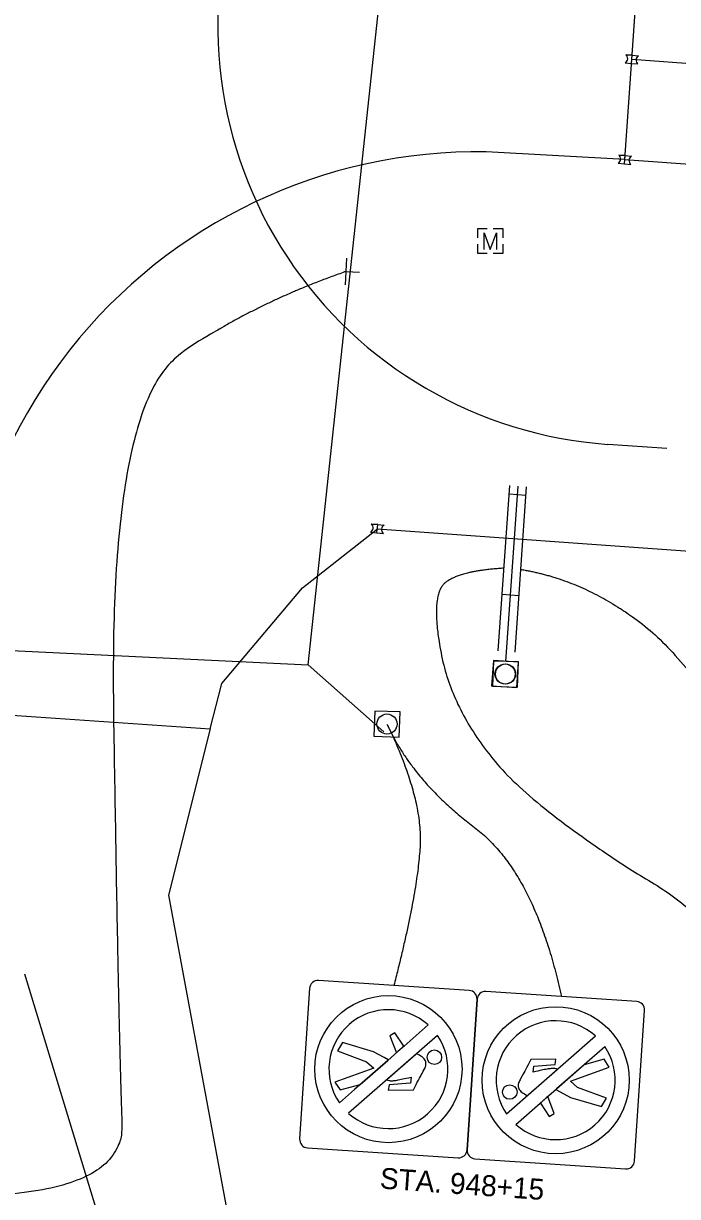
# Model space of a CAD drawing. Extents: x 1847379 to 1850904, y 217032 to 220169.
# Drawn here: x 1848911.4 to 1848989.3, y 218737.1 to 218877.1 of the extents above; entities that cross this region are included whole.
import ezdxf

# ---------------------------------------------------------------- set-up
doc = ezdxf.new("R2010")
doc.units = 0
for name, color, linetype in [('BR_P_Gen_Approach_Slab_Hidden', 7, 'Continuous'), ('BR_P_Gen_Phase_Construction', 7, 'Continuous'), ('PM_P_Cells', 7, 'Continuous'), ('PM_P_Channelizing_Line', 7, 'Continuous'), ('PM_P_Dotted_Line', 7, 'Continuous'), ('PM_P_Edge_Line', 7, 'Continuous'), ('PM_P_Lane_Line', 7, 'Continuous'), ('PM_P_Stop_Line', 7, 'Continuous'), ('PM_X_Channelizing_Line', 7, 'Continuous'), ('PM_X_Stop_Line', 7, 'Continuous'), ('SG_X_Wiring', 7, 'Continuous'), ('SN_X_Cantilever_Overhead', 7, 'Continuous'), ('SN_X_Foundation', 7, 'Continuous'), ('SN_X_Public', 7, 'Continuous'), ('SN_X_Text', 7, 'Continuous'), ('SV_X_Mon_Cells_Found', 7, 'Continuous')]:
    doc.layers.add(name, color=color, linetype=linetype)

msp = doc.modelspace()

# ---------------------------------------------------------------- linework, layer by layer
at = {"layer": 'BR_P_Gen_Approach_Slab_Hidden'}
for p, q in [((1848933.64, 218792.93), (1848928.66, 218773.07)), ((1848928.66, 218773.07), (1848938.92, 218717.78))]:
    msp.add_line(p, q, dxfattribs=at)
at = {"layer": 'BR_P_Gen_Phase_Construction'}
msp.add_line((1848868.73, 218797.37), (1848933.64, 218792.93), dxfattribs=at)
at = {"layer": 'PM_P_Cells'}
for p, q in [((1848983.92, 218873.26), (1848983.16, 218873.33)), ((1848983.16, 218873.33), (1848983.92, 218873.26)), ((1848983.84, 218872.29), (1848983.92, 218873.26)), ((1848983.92, 218873.26), (1848984.69, 218873.19)), ((1848983.07, 218872.36), (1848983.84, 218872.29)), ((1848983.07, 218872.36), (1848983.84, 218872.29)), ((1848983.84, 218872.29), (1848984.6, 218872.22)), ((1848983.09, 218861.29), (1848982.32, 218861.36)), ((1848982.32, 218861.36), (1848983.09, 218861.29)), ((1848983, 218860.32), (1848983.09, 218861.29)), ((1848983.09, 218861.29), (1848983.85, 218861.22)), ((1848982.23, 218860.39), (1848983, 218860.32)), ((1848982.23, 218860.39), (1848983, 218860.32)), ((1848983, 218860.32), (1848983.77, 218860.25)), ((1848953.59, 218817.28), (1848952.82, 218817.35)), ((1848952.82, 218817.35), (1848953.59, 218817.28)), ((1848953.5, 218816.31), (1848953.59, 218817.28)), ((1848953.59, 218817.28), (1848954.36, 218817.21)), ((1848952.73, 218816.38), (1848953.5, 218816.31)), ((1848952.73, 218816.38), (1848953.5, 218816.31)), ((1848953.5, 218816.31), (1848954.27, 218816.24))]:
    msp.add_line(p, q, dxfattribs=at)
for centre, start, end in [((1848982.81, 218872.87), 296.8063, 52.8586), ((1848982.81, 218872.87), 296.8063, 52.8586), ((1848984.95, 218872.68), 116.8063, 232.8586), ((1848981.97, 218860.9), 296.8063, 52.8586), ((1848981.97, 218860.9), 296.8063, 52.8586), ((1848984.11, 218860.71), 116.8063, 232.8586), ((1848952.47, 218816.89), 296.8063, 52.8586), ((1848952.47, 218816.89), 296.8063, 52.8586), ((1848954.62, 218816.7), 116.8063, 232.8586)]:
    msp.add_arc(centre, 0.576, start, end, dxfattribs=at)
at = {"layer": 'PM_P_Channelizing_Line'}
msp.add_line((1848983.04, 218860.81), (1849486.82, 218824.85), dxfattribs=at)
at = {"layer": 'PM_P_Dotted_Line'}
for p, q in [((1848983.04, 218860.81), (1848966.52, 218861.75)), ((1848988.03, 218826.36), (1848981, 218826.85))]:
    msp.add_line(p, q, dxfattribs=at)
for centre, radius, start, end in [((1848984.54, 218876.73), 50, 160.9794, 265.9392), ((1848965.57, 218799.82), 61.94, 89.125, 194.5243)]:
    msp.add_arc(centre, radius, start, end, dxfattribs=at)
at = {"layer": 'PM_P_Edge_Line'}
msp.add_line((1848953.55, 218816.79), (1849519.44, 218776.41), dxfattribs=at)
at = {"layer": 'PM_P_Lane_Line'}
msp.add_line((1848983.9, 218872.78), (1849487.67, 218836.82), dxfattribs=at)
at = {"layer": 'PM_P_Stop_Line'}
msp.add_line((1848983.04, 218860.81), (1848984.72, 218884.75), dxfattribs=at)
at = {"layer": 'PM_X_Channelizing_Line'}
msp.add_lwpolyline([(1848911.49, 218763.7), (1848928.55, 218707.66), (1848943.83, 218656.11), (1848955.22, 218618.44), (1848971.95, 218561.87), (1848985.85, 218514.54), (1849001.62, 218461.72), (1849015.55, 218410.53), (1849029.52, 218359.59)], dxfattribs=at)
at = {"layer": 'PM_X_Stop_Line'}
for p, q in [((1848944.63, 218809.74), (1848953.55, 218816.79)), ((1848935, 218798.33), (1848944.63, 218809.74)), ((1848933.64, 218792.93), (1848935, 218798.33))]:
    msp.add_line(p, q, dxfattribs=at)
at = {"layer": 'SG_X_Wiring'}
for p, q in [((1848945.32, 218800.54), (1848954.76, 218888.78)), ((1848847.49, 218805.29), (1848945.32, 218800.54)), ((1848945.32, 218800.54), (1848954.34, 218792.57))]:
    msp.add_line(p, q, dxfattribs=at)
at = {"layer": 'SN_X_Cantilever_Overhead'}
for p, q in [((1848968.87, 218800.96), (1848970.34, 218821.87)), ((1848969.27, 218820.94), (1848971.26, 218820.8)), ((1848968.43, 218808.97), (1848970.43, 218808.83))]:
    msp.add_line(p, q, dxfattribs=at)
msp.add_lwpolyline([(1848970.16, 218797.86), (1848970.37, 218800.86), (1848967.38, 218801.07), (1848967.17, 218798.07)], close=True, dxfattribs=at)
msp.add_circle((1848968.77, 218799.46), 1.2, dxfattribs=at)
at = {"layer": 'SN_X_Foundation'}
for points in [[(1848970.27, 218797.91), (1848970.38, 218800.9), (1848967.38, 218801.01), (1848967.27, 218798.01)], [(1848956.14, 218791.94), (1848956.25, 218794.94), (1848953.25, 218795.05), (1848953.14, 218792.05)]]:
    msp.add_lwpolyline(points, close=True, dxfattribs=at)
for centre in [(1848968.83, 218799.46), (1848954.7, 218793.5)]:
    msp.add_circle(centre, 1.2, dxfattribs=at)
at = {"layer": 'SN_X_Public'}
for p, q in [((1848949.77, 218845.88), (1848949.92, 218849.08)), ((1848949.85, 218847.48), (1848951.44, 218847.4)), ((1848967.96, 218802.23), (1848969.34, 218821.93)), ((1848969.96, 218802.09), (1848971.33, 218821.8)), ((1848960.73, 218756.35), (1848950.13, 218747.07)), ((1848955.65, 218756.68), (1848955.04, 218756.31)), ((1848955.65, 218756.68), (1848955.04, 218756.31)), ((1848955.04, 218756.31), (1848955.82, 218754.29)), ((1848955.04, 218756.31), (1848955.82, 218754.29)), ((1848956.7, 218755.06), (1848955.65, 218756.68)), ((1848956.7, 218755.06), (1848955.65, 218756.68)), ((1848968.95, 218747.02), (1848979.55, 218756.3)), ((1848949.4, 218755.5), (1848948.82, 218754.51)), ((1848949.4, 218755.5), (1848948.82, 218754.51)), ((1848953.11, 218754.42), (1848949.4, 218755.5)), ((1848953.11, 218754.42), (1848949.4, 218755.5)), ((1848948.82, 218754.51), (1848952.27, 218753.23)), ((1848948.82, 218754.51), (1848952.27, 218753.23)), ((1848954.35, 218753.73), (1848953.11, 218754.42)), ((1848954.35, 218753.73), (1848953.11, 218754.42)), ((1848954.84, 218753.43), (1848954.35, 218753.73)), ((1848954.84, 218753.43), (1848954.35, 218753.73)), ((1848958.12, 218754.07), (1848954.69, 218751.06)), ((1848955.82, 218754.29), (1848956, 218754.45)), ((1848958.23, 218754.16), (1848958.12, 218754.07)), ((1848974.84, 218753.52), (1848971.84, 218753.49)), ((1848974.84, 218753.52), (1848971.84, 218753.49)), ((1848974.74, 218752.89), (1848974.84, 218753.52)), ((1848974.74, 218752.89), (1848974.84, 218753.52)), ((1848980.57, 218753.51), (1848978.18, 218752.87)), ((1848980.57, 218753.51), (1848978.18, 218752.87)), ((1848981.18, 218752.58), (1848980.57, 218753.51)), ((1848981.18, 218752.58), (1848980.57, 218753.51)), ((1848953.13, 218752.46), (1848948.49, 218750.79)), ((1848953.13, 218752.46), (1848948.49, 218750.79)), ((1848951.5, 218750.5), (1848954.78, 218753.38)), ((1848952.27, 218753.23), (1848953.13, 218752.46)), ((1848952.27, 218753.23), (1848953.13, 218752.46)), ((1848954.78, 218753.38), (1848954.84, 218753.43)), ((1848971.56, 218749.3), (1848974.98, 218752.3)), ((1848971.84, 218753.49), (1848971.84, 218753.47)), ((1848971.84, 218753.49), (1848971.84, 218753.47)), ((1848972.11, 218751.96), (1848972.19, 218752.69)), ((1848972.11, 218751.96), (1848972.19, 218752.69)), ((1848972.19, 218752.69), (1848974.74, 218752.89)), ((1848972.19, 218752.69), (1848974.74, 218752.89)), ((1848978.18, 218752.87), (1848974.9, 218749.99)), ((1848976.55, 218750.91), (1848981.18, 218752.58)), ((1848976.55, 218750.91), (1848981.18, 218752.58)), ((1848948.49, 218750.79), (1848949.11, 218749.86)), ((1848948.49, 218750.79), (1848949.11, 218749.86)), ((1848957.57, 218751.4), (1848957.49, 218750.68)), ((1848957.57, 218751.4), (1848957.49, 218750.68)), ((1848977.41, 218750.14), (1848976.55, 218750.91)), ((1848977.41, 218750.14), (1848976.55, 218750.91)), ((1848949.11, 218749.86), (1848951.5, 218750.5)), ((1848949.11, 218749.86), (1848951.5, 218750.5)), ((1848954.94, 218750.48), (1848954.84, 218749.84)), ((1848954.94, 218750.48), (1848954.84, 218749.84)), ((1848954.84, 218749.84), (1848957.84, 218749.88)), ((1848954.84, 218749.84), (1848957.84, 218749.88)), ((1848957.49, 218750.68), (1848954.94, 218750.48)), ((1848957.49, 218750.68), (1848954.94, 218750.48)), ((1848957.84, 218749.88), (1848957.84, 218749.89)), ((1848957.84, 218749.88), (1848957.84, 218749.89)), ((1848971.45, 218749.2), (1848971.56, 218749.3)), ((1848974.9, 218749.99), (1848974.83, 218749.93)), ((1848974.83, 218749.93), (1848975.33, 218749.63)), ((1848974.83, 218749.93), (1848975.33, 218749.63)), ((1848975.33, 218749.63), (1848976.57, 218748.95)), ((1848975.33, 218749.63), (1848976.57, 218748.95)), ((1848980.86, 218748.86), (1848977.41, 218750.14)), ((1848980.86, 218748.86), (1848977.41, 218750.14)), ((1848972.98, 218748.3), (1848974.03, 218746.69)), ((1848972.98, 218748.3), (1848974.03, 218746.69)), ((1848973.86, 218749.08), (1848973.68, 218748.92)), ((1848974.64, 218747.06), (1848973.86, 218749.08)), ((1848974.64, 218747.06), (1848973.86, 218749.08)), ((1848976.57, 218748.95), (1848980.28, 218747.87)), ((1848976.57, 218748.95), (1848980.28, 218747.87)), ((1848980.28, 218747.87), (1848980.86, 218748.86)), ((1848980.28, 218747.87), (1848980.86, 218748.86)), ((1848974.03, 218746.69), (1848974.64, 218747.06)), ((1848974.03, 218746.69), (1848974.64, 218747.06))]:
    msp.add_line(p, q, dxfattribs=at)
for points in [[(1848945.47, 218761.98), (1848944.29, 218744.02)], [(1848964.5, 218761.73), (1848946.54, 218762.91)], [(1848965.43, 218760.66), (1848964.25, 218742.7)], [(1848964.25, 218742.7), (1848965.43, 218760.66)], [(1848984.46, 218760.41), (1848966.49, 218761.6)], [(1848984.2, 218741.39), (1848985.39, 218759.35)], [(1848959.61, 218757.62), (1848956.73, 218755.09), (1848956, 218754.44), (1848956, 218754.45)], [(1848956, 218754.45), (1848956.7, 218755.06), (1848956.7, 218755.06)], [(1848973.68, 218748.92), (1848974.9, 218749.99), (1848978.84, 218753.45), (1848980.65, 218755.04)], [(1848956, 218754.45), (1848954.78, 218753.38), (1848950.84, 218749.92), (1848949.03, 218748.33)], [(1848958.12, 218754.07), (1848958.12, 218754.07)], [(1848971.56, 218749.3), (1848971.56, 218749.3)], [(1848970.07, 218745.75), (1848972.94, 218748.27), (1848973.68, 218748.93), (1848973.68, 218748.92)], [(1848973.68, 218748.92), (1848972.98, 218748.3), (1848972.98, 218748.3)], [(1848945.22, 218742.96), (1848963.18, 218741.77)], [(1848965.18, 218741.64), (1848983.14, 218740.46)]]:
    msp.add_lwpolyline(points, dxfattribs=at)
for centre, radius in [((1848954.87, 218752.34), 8.77), ((1848974.8, 218751.02), 8.77), ((1848960.35, 218753.76), 0.864), ((1848969.33, 218749.61), 0.864)]:
    msp.add_circle(centre, radius, dxfattribs=at)
for centre, radius, start, end in [((1848946.47, 218761.91), 1, 86.2275, 176.2275), ((1848964.43, 218760.73), 1, 356.2275, 86.2275), ((1848966.43, 218760.6), 1, 86.2275, 176.2275), ((1848954.87, 218752.34), 7.09, 48.0755, 214.4755), ((1848954.87, 218752.34), 7.09, 48.0755, 214.4755), ((1848984.39, 218759.41), 1, 356.2275, 86.2275), ((1848974.8, 218751.02), 7.09, 48.0466, 214.3989), ((1848954.87, 218752.34), 7.09, 228.0466, 34.3989), ((1848974.8, 218751.02), 7.09, 228.0755, 34.4755), ((1848974.8, 218751.02), 7.09, 228.0755, 34.4755), ((1848945.29, 218743.95), 1, 176.2275, 266.2275), ((1848963.25, 218742.77), 1, 266.2275, 356.2275), ((1848965.24, 218742.64), 1, 176.2275, 266.2275), ((1848983.21, 218741.45), 1, 266.2275, 356.2275)]:
    msp.add_arc(centre, radius, start, end, dxfattribs=at)
for points, degree in [([(1848949.85, 218847.48), (1848938.73, 218843.63), (1848921.54, 218831.73), (1848922.68, 218757.56), (1848923.54, 218734.09), (1848886.76, 218738.28)], 2), ([(1848968.65, 218812.08), (1848963.26, 218811.77), (1848959.87, 218808.8), (1848962.37, 218795.34), (1848972.61, 218782.93), (1849002.07, 218764.9), (1849001.83, 218733.74)], 2), ([(1848970.64, 218811.94), (1848978.12, 218810.73), (1848991.68, 218800.45), (1849010.03, 218768.73), (1849033.87, 218749.22), (1849035.6, 218731.52)], 2), ([(1848954.7, 218793.5), (1848957.8, 218786.68), (1848972.29, 218775.81), (1848975.48, 218761)], 2), ([(1848954.7, 218793.5), (1848958.95, 218784.71), (1848958.34, 218773.29), (1848955.52, 218762.32)], 2), ([(1848957.84, 218749.89), (1848958.29, 218750.75), (1848959.01, 218752.09), (1848959.28, 218752.58), (1848959.32, 218752.75), (1848959.33, 218752.92), (1848959.36, 218753.32), (1848958.92, 218753.85), (1848958.49, 218754.04), (1848958.23, 218754.16)], 3), ([(1848957.84, 218749.89), (1848958.29, 218750.75), (1848959.01, 218752.09), (1848959.28, 218752.58), (1848959.32, 218752.75), (1848959.33, 218752.92), (1848959.36, 218753.32), (1848958.92, 218753.85), (1848958.49, 218754.04), (1848958.23, 218754.16)], 3), ([(1848971.84, 218753.47), (1848971.39, 218752.62), (1848970.67, 218751.27), (1848970.4, 218750.78), (1848970.36, 218750.62), (1848970.34, 218750.45), (1848970.32, 218750.05), (1848970.76, 218749.51), (1848971.18, 218749.33), (1848971.45, 218749.2)], 3), ([(1848971.84, 218753.47), (1848971.39, 218752.62), (1848970.67, 218751.27), (1848970.4, 218750.78), (1848970.36, 218750.62), (1848970.34, 218750.45), (1848970.32, 218750.05), (1848970.76, 218749.51), (1848971.18, 218749.33), (1848971.45, 218749.2)], 3), ([(1848974.98, 218752.3), (1848974.92, 218752.34), (1848974.72, 218752.42), (1848974.26, 218752.41), (1848973.84, 218752.36), (1848973.1, 218752.21), (1848972.59, 218752.09), (1848972.11, 218751.96)], 3), ([(1848974.98, 218752.3), (1848974.92, 218752.34), (1848974.72, 218752.42), (1848974.26, 218752.41), (1848973.84, 218752.36), (1848973.1, 218752.21), (1848972.59, 218752.09), (1848972.11, 218751.96)], 3), ([(1848954.69, 218751.06), (1848954.76, 218751.03), (1848954.96, 218750.95), (1848955.42, 218750.95), (1848955.84, 218751.01), (1848956.58, 218751.16), (1848957.09, 218751.28), (1848957.57, 218751.4)], 3), ([(1848954.69, 218751.06), (1848954.76, 218751.03), (1848954.96, 218750.95), (1848955.42, 218750.95), (1848955.84, 218751.01), (1848956.58, 218751.16), (1848957.09, 218751.28), (1848957.57, 218751.4)], 3)]:
    msp.add_open_spline(points, degree=degree, dxfattribs=at)
at = {"layer": 'SV_X_Mon_Cells_Found'}
msp.add_line((1848967.01, 218851.1), (1848967.01, 218851.1), dxfattribs=at)
for points in [[(1848965.51, 218851.48), (1848965.51, 218852.6), (1848966.63, 218852.6)], [(1848966.27, 218850.1), (1848966.27, 218852.1), (1848967.01, 218850.1), (1848967.75, 218852.1), (1848967.75, 218850.1)], [(1848967.36, 218852.6), (1848968.51, 218852.6), (1848968.51, 218851.48)], [(1848966.63, 218849.6), (1848965.51, 218849.6), (1848965.51, 218850.72)], [(1848968.51, 218850.72), (1848968.51, 218849.6), (1848967.36, 218849.6)]]:
    msp.add_lwpolyline(points, dxfattribs=at)

# ---------------------------------------------------------------- texts
at = {"layer": 'SN_X_Text'}
msp.add_text('STA. 948+15', height=2.5, rotation=355.9402, dxfattribs=at).set_placement((1848953.79, 218738.11))

doc.saveas('drawing.dxf')
